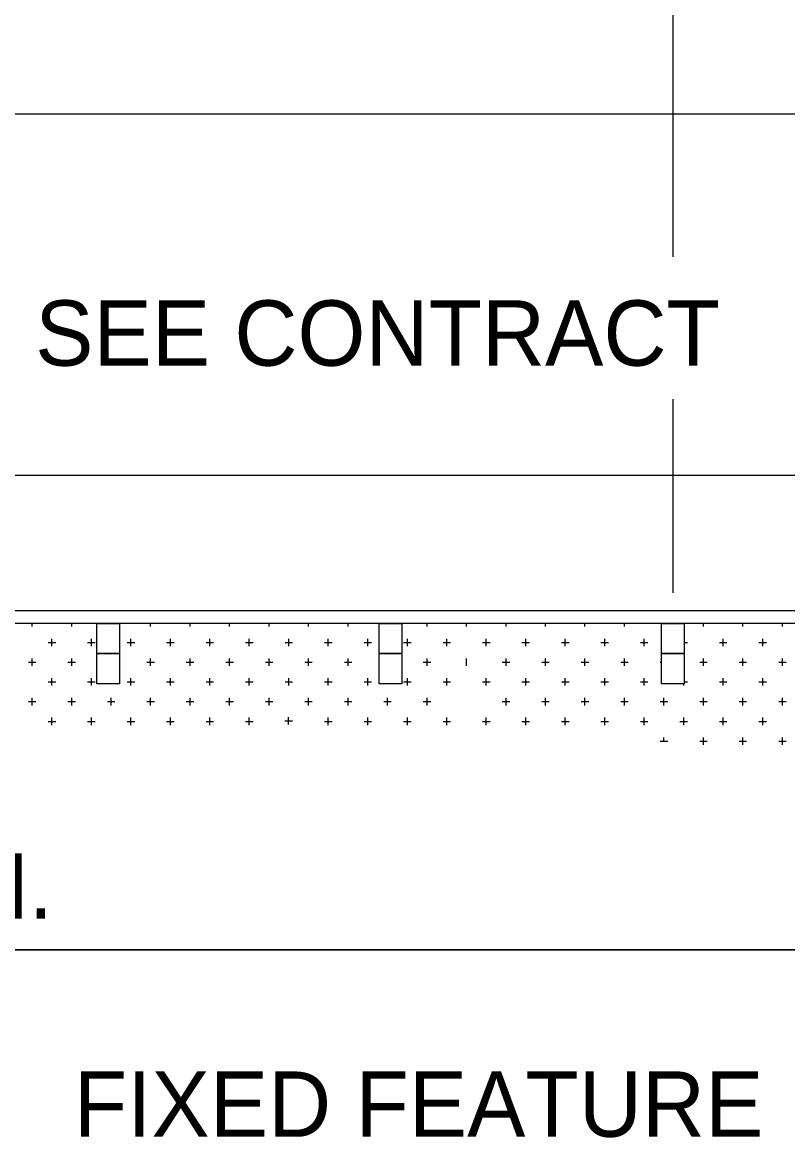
# Model space of a CAD drawing. Extents: x 1312564.5 to 1312581.5, y 1207298.4 to 1207309.4.
# Drawn here: x 1312568.156 to 1312569.093, y 1207306.665 to 1207308.031 of the extents above; entities that cross this region are included whole.
import ezdxf

# ---------------------------------------------------------------- set-up
doc = ezdxf.new("R2010")
doc.units = 0
for name, color, linetype in [('Level 15', 7, 'Continuous'), ('Level 2', 7, 'Continuous'), ('Level 20', 7, 'Continuous'), ('Level 3', 7, 'Continuous'), ('Level 4', 7, 'Continuous'), ('Level 44', 7, 'Continuous')]:
    doc.layers.add(name, color=color, linetype=linetype)

msp = doc.modelspace()

# ---------------------------------------------------------------- linework, layer by layer
at = {"layer": 'Level 15'}
msp.add_line((1312570.0398, 1207306.8953), (1312565.928, 1207306.8953), dxfattribs=at)
for points in [[(1312568.9523, 1207308.5818), (1312568.9523, 1207307.7435)], [(1312568.9523, 1207307.5693), (1312568.9523, 1207307.3322)], [(1312566.0799, 1207306.8953), (1312569.4069, 1207306.8953)]]:
    msp.add_lwpolyline(points, dxfattribs=at)
at = {"layer": 'Level 2'}
for p, q in [((1312570.0398, 1207307.31), (1312566.8787, 1207307.31)), ((1312570.0398, 1207307.2948), (1312566.8787, 1207307.2948))]:
    msp.add_line(p, q, dxfattribs=at)
for points in [[(1312568.2473, 1207307.2948), (1312568.275, 1207307.2948), (1312568.275, 1207307.2579), (1312568.2473, 1207307.2579)], [(1312568.5929, 1207307.2948), (1312568.6206, 1207307.2948), (1312568.6206, 1207307.2579), (1312568.5929, 1207307.2579)], [(1312568.9385, 1207307.2948), (1312568.9662, 1207307.2948), (1312568.9662, 1207307.2579), (1312568.9385, 1207307.2579)], [(1312568.2473, 1207307.2579), (1312568.275, 1207307.2579), (1312568.275, 1207307.221), (1312568.2473, 1207307.221)], [(1312568.5929, 1207307.2579), (1312568.6206, 1207307.2579), (1312568.6206, 1207307.221), (1312568.5929, 1207307.221)], [(1312568.9385, 1207307.2579), (1312568.9662, 1207307.2579), (1312568.9662, 1207307.221), (1312568.9385, 1207307.221)]]:
    msp.add_lwpolyline(points, close=True, dxfattribs=at)
at = {"layer": 'Level 3'}
msp.add_line((1312570.0398, 1207307.4759), (1312565.7882, 1207307.4759), dxfattribs=at)
at = {"layer": 'Level 4'}
for p, q in [((1312568.1682, 1207307.2911), (1312568.1682, 1207307.2948)), ((1312568.2165, 1207307.2911), (1312568.2165, 1207307.2948)), ((1312568.3131, 1207307.2911), (1312568.3131, 1207307.2948)), ((1312568.3615, 1207307.2911), (1312568.3615, 1207307.2948)), ((1312568.4098, 1207307.2911), (1312568.4098, 1207307.2948)), ((1312568.4581, 1207307.2911), (1312568.4581, 1207307.2948)), ((1312568.5064, 1207307.2911), (1312568.5064, 1207307.2948)), ((1312568.5548, 1207307.2911), (1312568.5548, 1207307.2948)), ((1312568.6514, 1207307.2911), (1312568.6514, 1207307.2948)), ((1312568.6997, 1207307.2911), (1312568.6997, 1207307.2948)), ((1312568.7481, 1207307.2911), (1312568.7481, 1207307.2948)), ((1312568.7964, 1207307.2911), (1312568.7964, 1207307.2948)), ((1312568.8447, 1207307.2911), (1312568.8447, 1207307.2948)), ((1312568.8931, 1207307.2911), (1312568.8931, 1207307.2948)), ((1312568.9897, 1207307.2911), (1312568.9897, 1207307.2948)), ((1312569.038, 1207307.2911), (1312569.038, 1207307.2948)), ((1312569.0864, 1207307.2911), (1312569.0864, 1207307.2948)), ((1312568.1923, 1207307.2715), (1312568.1923, 1207307.2761)), ((1312568.2406, 1207307.2715), (1312568.2406, 1207307.2761)), ((1312568.289, 1207307.2715), (1312568.289, 1207307.2761)), ((1312568.3373, 1207307.2715), (1312568.3373, 1207307.2761)), ((1312568.3856, 1207307.2715), (1312568.3856, 1207307.2761)), ((1312568.4339, 1207307.2715), (1312568.4339, 1207307.2761)), ((1312568.4823, 1207307.2715), (1312568.4823, 1207307.2761)), ((1312568.5306, 1207307.2715), (1312568.5306, 1207307.2761)), ((1312568.5789, 1207307.2715), (1312568.5789, 1207307.2761)), ((1312568.6273, 1207307.2715), (1312568.6273, 1207307.2761)), ((1312568.6756, 1207307.2715), (1312568.6756, 1207307.2761)), ((1312568.7239, 1207307.2715), (1312568.7239, 1207307.2761)), ((1312568.7722, 1207307.2715), (1312568.7722, 1207307.2761)), ((1312568.8206, 1207307.2715), (1312568.8206, 1207307.2761)), ((1312568.8689, 1207307.2715), (1312568.8689, 1207307.2761)), ((1312568.9172, 1207307.2715), (1312568.9172, 1207307.2761)), ((1312569.0139, 1207307.2715), (1312569.0139, 1207307.2761)), ((1312569.0622, 1207307.2715), (1312569.0622, 1207307.2761)), ((1312568.1877, 1207307.2715), (1312568.1923, 1207307.2715)), ((1312568.1923, 1207307.2669), (1312568.1923, 1207307.2715)), ((1312568.1923, 1207307.2715), (1312568.1969, 1207307.2715)), ((1312568.236, 1207307.2715), (1312568.2452, 1207307.2715)), ((1312568.2406, 1207307.2669), (1312568.2406, 1207307.2715)), ((1312568.2844, 1207307.2715), (1312568.2936, 1207307.2715)), ((1312568.289, 1207307.2669), (1312568.289, 1207307.2715)), ((1312568.3327, 1207307.2715), (1312568.3419, 1207307.2715)), ((1312568.3373, 1207307.2669), (1312568.3373, 1207307.2715)), ((1312568.381, 1207307.2715), (1312568.3902, 1207307.2715)), ((1312568.3856, 1207307.2669), (1312568.3856, 1207307.2715)), ((1312568.4293, 1207307.2715), (1312568.4386, 1207307.2715)), ((1312568.4339, 1207307.2669), (1312568.4339, 1207307.2715)), ((1312568.4777, 1207307.2715), (1312568.4823, 1207307.2715)), ((1312568.4823, 1207307.2669), (1312568.4823, 1207307.2715)), ((1312568.4823, 1207307.2715), (1312568.4869, 1207307.2715)), ((1312568.526, 1207307.2715), (1312568.5352, 1207307.2715)), ((1312568.5306, 1207307.2669), (1312568.5306, 1207307.2715)), ((1312568.5743, 1207307.2715), (1312568.5835, 1207307.2715)), ((1312568.5789, 1207307.2669), (1312568.5789, 1207307.2715)), ((1312568.6226, 1207307.2715), (1312568.6319, 1207307.2715)), ((1312568.6273, 1207307.2669), (1312568.6273, 1207307.2715)), ((1312568.671, 1207307.2715), (1312568.6802, 1207307.2715)), ((1312568.6756, 1207307.2669), (1312568.6756, 1207307.2715)), ((1312568.7193, 1207307.2715), (1312568.7285, 1207307.2715)), ((1312568.7239, 1207307.2669), (1312568.7239, 1207307.2715)), ((1312568.7676, 1207307.2715), (1312568.7722, 1207307.2715)), ((1312568.7722, 1207307.2669), (1312568.7722, 1207307.2715)), ((1312568.7722, 1207307.2715), (1312568.7768, 1207307.2715)), ((1312568.816, 1207307.2715), (1312568.8252, 1207307.2715)), ((1312568.8206, 1207307.2669), (1312568.8206, 1207307.2715)), ((1312568.8643, 1207307.2715), (1312568.8735, 1207307.2715)), ((1312568.8689, 1207307.2669), (1312568.8689, 1207307.2715)), ((1312568.9126, 1207307.2715), (1312568.9218, 1207307.2715)), ((1312568.9172, 1207307.2669), (1312568.9172, 1207307.2715)), ((1312568.9662, 1207307.2715), (1312568.9702, 1207307.2715)), ((1312569.0093, 1207307.2715), (1312569.0185, 1207307.2715)), ((1312569.0139, 1207307.2669), (1312569.0139, 1207307.2715)), ((1312569.0576, 1207307.2715), (1312569.0622, 1207307.2715)), ((1312569.0622, 1207307.2669), (1312569.0622, 1207307.2715)), ((1312569.0622, 1207307.2715), (1312569.0668, 1207307.2715)), ((1312568.1635, 1207307.2473), (1312568.1728, 1207307.2473)), ((1312568.1682, 1207307.2427), (1312568.1682, 1207307.252)), ((1312568.2119, 1207307.2473), (1312568.2211, 1207307.2473)), ((1312568.2165, 1207307.2427), (1312568.2165, 1207307.252)), ((1312568.3085, 1207307.2473), (1312568.3177, 1207307.2473)), ((1312568.3131, 1207307.2427), (1312568.3131, 1207307.252)), ((1312568.3568, 1207307.2473), (1312568.3661, 1207307.2473)), ((1312568.3615, 1207307.2427), (1312568.3615, 1207307.252)), ((1312568.4052, 1207307.2473), (1312568.4144, 1207307.2473)), ((1312568.4098, 1207307.2427), (1312568.4098, 1207307.252)), ((1312568.4535, 1207307.2473), (1312568.4627, 1207307.2473)), ((1312568.4581, 1207307.2427), (1312568.4581, 1207307.252)), ((1312568.5018, 1207307.2473), (1312568.511, 1207307.2473)), ((1312568.5064, 1207307.2427), (1312568.5064, 1207307.252)), ((1312568.5502, 1207307.2473), (1312568.5594, 1207307.2473)), ((1312568.5548, 1207307.2427), (1312568.5548, 1207307.252)), ((1312568.6468, 1207307.2473), (1312568.656, 1207307.2473)), ((1312568.6514, 1207307.2427), (1312568.6514, 1207307.252)), ((1312568.6997, 1207307.2427), (1312568.6997, 1207307.252)), ((1312568.7435, 1207307.2473), (1312568.7527, 1207307.2473)), ((1312568.7481, 1207307.2427), (1312568.7481, 1207307.252)), ((1312568.7918, 1207307.2473), (1312568.801, 1207307.2473)), ((1312568.7964, 1207307.2427), (1312568.7964, 1207307.252)), ((1312568.8401, 1207307.2473), (1312568.8493, 1207307.2473)), ((1312568.8447, 1207307.2427), (1312568.8447, 1207307.252)), ((1312568.8884, 1207307.2473), (1312568.8977, 1207307.2473)), ((1312568.8931, 1207307.2427), (1312568.8931, 1207307.252)), ((1312568.9368, 1207307.2473), (1312568.9385, 1207307.2473)), ((1312568.9851, 1207307.2473), (1312568.9943, 1207307.2473)), ((1312568.9897, 1207307.2427), (1312568.9897, 1207307.252)), ((1312569.0334, 1207307.2473), (1312569.0426, 1207307.2473)), ((1312569.038, 1207307.2427), (1312569.038, 1207307.252)), ((1312569.0818, 1207307.2473), (1312569.091, 1207307.2473)), ((1312569.0864, 1207307.2427), (1312569.0864, 1207307.252)), ((1312568.1877, 1207307.2232), (1312568.1923, 1207307.2232)), ((1312568.1923, 1207307.2186), (1312568.1923, 1207307.2278)), ((1312568.1923, 1207307.2232), (1312568.1969, 1207307.2232)), ((1312568.236, 1207307.2232), (1312568.2452, 1207307.2232)), ((1312568.2406, 1207307.2186), (1312568.2406, 1207307.2278)), ((1312568.2844, 1207307.2232), (1312568.2936, 1207307.2232)), ((1312568.289, 1207307.2186), (1312568.289, 1207307.2278)), ((1312568.3327, 1207307.2232), (1312568.3419, 1207307.2232)), ((1312568.3373, 1207307.2186), (1312568.3373, 1207307.2278)), ((1312568.381, 1207307.2232), (1312568.3902, 1207307.2232)), ((1312568.3856, 1207307.2186), (1312568.3856, 1207307.2278)), ((1312568.4293, 1207307.2232), (1312568.4386, 1207307.2232)), ((1312568.4339, 1207307.2186), (1312568.4339, 1207307.2278)), ((1312568.4777, 1207307.2232), (1312568.4823, 1207307.2232)), ((1312568.4823, 1207307.2186), (1312568.4823, 1207307.2278)), ((1312568.4823, 1207307.2232), (1312568.4869, 1207307.2232)), ((1312568.526, 1207307.2232), (1312568.5352, 1207307.2232)), ((1312568.5306, 1207307.2186), (1312568.5306, 1207307.2278)), ((1312568.5743, 1207307.2232), (1312568.5835, 1207307.2232)), ((1312568.5789, 1207307.2186), (1312568.5789, 1207307.2278)), ((1312568.6226, 1207307.2232), (1312568.6319, 1207307.2232)), ((1312568.6273, 1207307.2186), (1312568.6273, 1207307.2278)), ((1312568.671, 1207307.2232), (1312568.6802, 1207307.2232)), ((1312568.6756, 1207307.2186), (1312568.6756, 1207307.2278)), ((1312568.7193, 1207307.2232), (1312568.7285, 1207307.2232)), ((1312568.7239, 1207307.2186), (1312568.7239, 1207307.2278)), ((1312568.7676, 1207307.2232), (1312568.7722, 1207307.2232)), ((1312568.7722, 1207307.2186), (1312568.7722, 1207307.2278)), ((1312568.7722, 1207307.2232), (1312568.7768, 1207307.2232)), ((1312568.816, 1207307.2232), (1312568.8252, 1207307.2232)), ((1312568.8206, 1207307.2186), (1312568.8206, 1207307.2278)), ((1312568.8643, 1207307.2232), (1312568.8735, 1207307.2232)), ((1312568.8689, 1207307.2186), (1312568.8689, 1207307.2278)), ((1312568.9126, 1207307.2232), (1312568.9218, 1207307.2232)), ((1312568.9172, 1207307.2186), (1312568.9172, 1207307.2278)), ((1312568.9655, 1207307.2186), (1312568.9655, 1207307.221)), ((1312568.9662, 1207307.2232), (1312568.9702, 1207307.2232)), ((1312569.0093, 1207307.2232), (1312569.0185, 1207307.2232)), ((1312569.0139, 1207307.2186), (1312569.0139, 1207307.2278)), ((1312569.0576, 1207307.2232), (1312569.0622, 1207307.2232)), ((1312569.0622, 1207307.2186), (1312569.0622, 1207307.2278)), ((1312569.0622, 1207307.2232), (1312569.0668, 1207307.2232)), ((1312568.1635, 1207307.199), (1312568.1728, 1207307.199)), ((1312568.1682, 1207307.1944), (1312568.1682, 1207307.2036)), ((1312568.2119, 1207307.199), (1312568.2211, 1207307.199)), ((1312568.2165, 1207307.1944), (1312568.2165, 1207307.2036)), ((1312568.2602, 1207307.199), (1312568.2694, 1207307.199)), ((1312568.2648, 1207307.1944), (1312568.2648, 1207307.2036)), ((1312568.3085, 1207307.199), (1312568.3177, 1207307.199)), ((1312568.3131, 1207307.1944), (1312568.3131, 1207307.2036)), ((1312568.3568, 1207307.199), (1312568.3661, 1207307.199)), ((1312568.3615, 1207307.1944), (1312568.3615, 1207307.2036)), ((1312568.4052, 1207307.199), (1312568.4144, 1207307.199)), ((1312568.4098, 1207307.1944), (1312568.4098, 1207307.2036)), ((1312568.4535, 1207307.199), (1312568.4627, 1207307.199)), ((1312568.4581, 1207307.1944), (1312568.4581, 1207307.2036)), ((1312568.5018, 1207307.199), (1312568.511, 1207307.199)), ((1312568.5064, 1207307.1944), (1312568.5064, 1207307.2036)), ((1312568.5502, 1207307.199), (1312568.5594, 1207307.199)), ((1312568.5548, 1207307.1944), (1312568.5548, 1207307.2036)), ((1312568.5985, 1207307.199), (1312568.6077, 1207307.199)), ((1312568.6031, 1207307.1944), (1312568.6031, 1207307.2036)), ((1312568.6468, 1207307.199), (1312568.656, 1207307.199)), ((1312568.6514, 1207307.1944), (1312568.6514, 1207307.2036)), ((1312568.7435, 1207307.199), (1312568.7527, 1207307.199)), ((1312568.7481, 1207307.1944), (1312568.7481, 1207307.2036)), ((1312568.7918, 1207307.199), (1312568.801, 1207307.199)), ((1312568.7964, 1207307.1944), (1312568.7964, 1207307.2036)), ((1312568.8401, 1207307.199), (1312568.8493, 1207307.199)), ((1312568.8447, 1207307.1944), (1312568.8447, 1207307.2036)), ((1312568.8884, 1207307.199), (1312568.8977, 1207307.199)), ((1312568.8931, 1207307.1944), (1312568.8931, 1207307.2036)), ((1312568.9368, 1207307.199), (1312568.946, 1207307.199)), ((1312568.9414, 1207307.1944), (1312568.9414, 1207307.2036)), ((1312568.9851, 1207307.199), (1312568.9943, 1207307.199)), ((1312568.9897, 1207307.1944), (1312568.9897, 1207307.2036)), ((1312569.0334, 1207307.199), (1312569.0426, 1207307.199)), ((1312569.038, 1207307.1944), (1312569.038, 1207307.2036)), ((1312569.0818, 1207307.199), (1312569.091, 1207307.199)), ((1312569.0864, 1207307.1944), (1312569.0864, 1207307.2036)), ((1312568.1923, 1207307.1702), (1312568.1923, 1207307.1795)), ((1312568.2406, 1207307.1702), (1312568.2406, 1207307.1795)), ((1312568.289, 1207307.1702), (1312568.289, 1207307.1795)), ((1312568.3373, 1207307.1702), (1312568.3373, 1207307.1795)), ((1312568.3856, 1207307.1702), (1312568.3856, 1207307.1795)), ((1312568.4339, 1207307.1702), (1312568.4339, 1207307.1795)), ((1312568.482, 1207307.1709), (1312568.482, 1207307.1801)), ((1312568.5306, 1207307.1702), (1312568.5306, 1207307.1795)), ((1312568.5789, 1207307.1702), (1312568.5789, 1207307.1795)), ((1312568.6273, 1207307.1702), (1312568.6273, 1207307.1795)), ((1312568.6756, 1207307.1702), (1312568.6756, 1207307.1795)), ((1312568.7239, 1207307.1702), (1312568.7239, 1207307.1795)), ((1312568.7722, 1207307.1702), (1312568.7722, 1207307.1795)), ((1312568.8206, 1207307.1702), (1312568.8206, 1207307.1795)), ((1312568.8689, 1207307.1702), (1312568.8689, 1207307.1795)), ((1312568.9172, 1207307.1702), (1312568.9172, 1207307.1795)), ((1312568.9655, 1207307.1702), (1312568.9655, 1207307.1795)), ((1312569.0139, 1207307.1702), (1312569.0139, 1207307.1795)), ((1312569.0622, 1207307.1702), (1312569.0622, 1207307.1795)), ((1312568.1877, 1207307.1749), (1312568.1923, 1207307.1749)), ((1312568.1923, 1207307.1749), (1312568.1969, 1207307.1749)), ((1312568.236, 1207307.1749), (1312568.2452, 1207307.1749)), ((1312568.2844, 1207307.1749), (1312568.2936, 1207307.1749)), ((1312568.3327, 1207307.1749), (1312568.3419, 1207307.1749)), ((1312568.381, 1207307.1749), (1312568.3902, 1207307.1749)), ((1312568.4293, 1207307.1749), (1312568.4386, 1207307.1749)), ((1312568.4774, 1207307.1755), (1312568.4866, 1207307.1755)), ((1312568.526, 1207307.1749), (1312568.5352, 1207307.1749)), ((1312568.5743, 1207307.1749), (1312568.5835, 1207307.1749)), ((1312568.6226, 1207307.1749), (1312568.6319, 1207307.1749)), ((1312568.671, 1207307.1749), (1312568.6802, 1207307.1749)), ((1312568.7193, 1207307.1749), (1312568.7285, 1207307.1749)), ((1312568.7676, 1207307.1749), (1312568.7722, 1207307.1749)), ((1312568.7722, 1207307.1749), (1312568.7768, 1207307.1749)), ((1312568.816, 1207307.1749), (1312568.8252, 1207307.1749)), ((1312568.8643, 1207307.1749), (1312568.8735, 1207307.1749)), ((1312568.9126, 1207307.1749), (1312568.9218, 1207307.1749)), ((1312568.9609, 1207307.1749), (1312568.9702, 1207307.1749)), ((1312569.0093, 1207307.1749), (1312569.0185, 1207307.1749)), ((1312569.0576, 1207307.1749), (1312569.0622, 1207307.1749)), ((1312569.0622, 1207307.1749), (1312569.0668, 1207307.1749)), ((1312568.9414, 1207307.1499), (1312568.9414, 1207307.1553)), ((1312568.9897, 1207307.1461), (1312568.9897, 1207307.1553)), ((1312569.038, 1207307.1461), (1312569.038, 1207307.1553)), ((1312569.0864, 1207307.1461), (1312569.0864, 1207307.1553)), ((1312568.9368, 1207307.1507), (1312568.946, 1207307.1507)), ((1312568.9851, 1207307.1507), (1312568.9943, 1207307.1507)), ((1312569.0334, 1207307.1507), (1312569.0426, 1207307.1507)), ((1312569.0818, 1207307.1507), (1312569.091, 1207307.1507))]:
    msp.add_line(p, q, dxfattribs=at)
at = {"layer": 'Level 44'}
msp.add_line((1312570.0398, 1207307.9183), (1312565.7882, 1207307.9183), dxfattribs=at)

# ---------------------------------------------------------------- texts
at = {"layer": 'Level 20'}
for s, p in [('SEE CONTRACT', (1312568.1718, 1207307.6103)), ("65'  MIN.", (1312567.769, 1207306.9335)), ('FIXED FEATURE', (1312568.219, 1207306.6663))]:
    msp.add_text(s, height=0.08, dxfattribs=at).set_placement(p)

doc.saveas('drawing.dxf')
